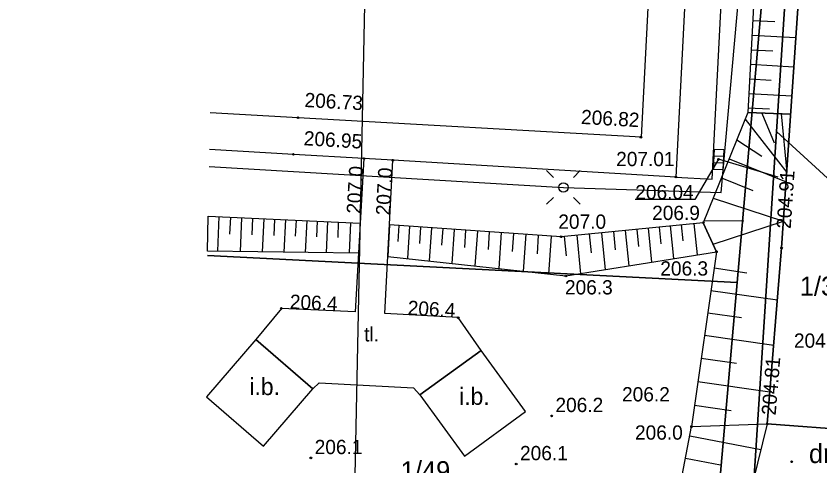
# Model space of a CAD drawing. Extents: x 6512400 to 6513200, y 6022500 to 6022750.
# Drawn here: x 6512691.61 to 6512733.85, y 6022618.44 to 6022642.07 of the extents above; entities that cross this region are included whole.
import ezdxf

# ---------------------------------------------------------------- set-up
doc = ezdxf.new("R2010")
doc.units = 0
for name, color, linetype in [('000 Inne (niezydentyfikowane)', 7, 'Continuous'), ('210-oznaczenie konturu użytku gruntowego', 7, 'Continuous'), ('211-numer działki ewidencyjnej', 7, 'Continuous'), ('217-kontur klasyfikacyjny', 7, 'Continuous'), ('218-kontur użytku gruntowego', 7, 'Continuous'), ('219-działka ewidencyjna', 7, 'Continuous'), ('chodnik (powierzchnia)', 7, 'Continuous'), ('inna budowla (powierzchnia)', 7, 'Continuous'), ('inna budowla (powierzchnia)-Atr17', 7, 'Continuous'), ('jezdnia', 7, 'Continuous'), ('jezdnia (powierzchnia)', 7, 'Continuous'), ('kratka ściekowa (punkt)', 7, 'Continuous'), ('krawężnik (linia)', 7, 'Continuous'), ('latarnia (punkt)', 7, 'Continuous'), ('Obszar opracowania', 7, 'Continuous'), ('pikieta naturalna', 7, 'Continuous'), ('pikieta naturalna-Atr2', 7, 'Continuous'), ('pikieta sztuczna', 7, 'Continuous'), ('pikieta sztuczna-Atr2', 7, 'Continuous'), ('plac (powierzchnia)', 7, 'Continuous'), ('plac (powierzchnia)-Atr17', 7, 'Continuous'), ('przewód elektroenergetyczny (linia)', 7, 'Continuous'), ('przewód kanalizacyjny (linia)', 7, 'Continuous'), ('punkt o określonej wysokości (sieć kanalizacyjna)', 7, 'Continuous'), ('punkt o określonej wysokości (sieć kanalizacyjna)-Atr2', 7, 'Continuous'), ('punkt wysokościowy naturalny', 7, 'Continuous'), ('punkt wysokościowy naturalny-Atr2', 7, 'Continuous'), ('punkt wysokościowy sztuczny', 7, 'Continuous'), ('punkt wysokościowy sztuczny-Atr2', 7, 'Continuous'), ('skarpa nieumocniona', 7, 'Continuous'), ('skarpa nieumocniona (powierzchnia)', 7, 'Continuous')]:
    doc.layers.add(name, color=color, linetype=linetype)

# ---------------------------------------------------------------- blocks, each defined once
blk = doc.blocks.new('PW01')
blk.add_circle((0, 0), 0.045)
blk = doc.blocks.new('PW02')
blk.add_circle((0, 0), 0.045)
blk = doc.blocks.new('US05')
for p, q in [((-0.525, -0.25), (-0.525, 0.25)), ((-0.525, 0.25), (-0.175, 0.25)), ((-0.175, -0.25), (-0.175, 0.25)), ((-0.175, 0.25), (0.175, 0.25)), ((0.175, -0.25), (0.175, 0.25)), ((0.175, 0.25), (0.525, 0.25)), ((0.525, -0.25), (0.525, 0.25)), ((-0.525, -0.25), (-0.175, -0.25)), ((-0.175, -0.25), (0.175, -0.25)), ((0.175, -0.25), (0.525, -0.25))]:
    blk.add_line(p, q)
blk = doc.blocks.new('SM01')
for p, q in [((-0.53, 0.531), (-0.883, 0.884)), ((0.531, 0.531), (0.884, 0.884)), ((-0.53, -0.53), (-0.883, -0.883)), ((0.531, -0.53), (0.884, -0.883))]:
    blk.add_line(p, q)
blk.add_circle((0, 0), 0.25)

msp = doc.modelspace()

# ---------------------------------------------------------------- linework, layer by layer
at = {"layer": '000 Inne (niezydentyfikowane)'}
for p, q in [((6512702.27, 6022631.54), (6512702.19, 6022629.72)), ((6512702.87, 6022631.51), (6512702.83, 6022630.61)), ((6512703.46, 6022631.48), (6512703.38, 6022629.71)), ((6512704.04, 6022631.46), (6512704, 6022630.58)), ((6512704.62, 6022631.43), (6512704.54, 6022629.69)), ((6512705.19, 6022631.4), (6512705.16, 6022630.54)), ((6512705.76, 6022631.38), (6512705.68, 6022629.67)), ((6512706.32, 6022631.35), (6512706.28, 6022630.51)), ((6512706.88, 6022631.33), (6512706.8, 6022629.66)), ((6512707.43, 6022631.3), (6512707.39, 6022630.48)), ((6512707.98, 6022631.28), (6512707.9, 6022629.64)), ((6512708.54, 6022631.25), (6512708.51, 6022630.44)), ((6512709.19, 6022631.22), (6512709.12, 6022629.63)), ((6512727.01, 6022620.02), (6512730.75, 6022619.31)), ((6512726.78, 6022618.84), (6512728.62, 6022618.49))]:
    msp.add_line(p, q, dxfattribs=at)
for points in [[(6512730.32, 6022641.85), (6512731.48, 6022641.79)], [(6512730.27, 6022641.07), (6512732.58, 6022640.95)], [(6512730.23, 6022640.3), (6512731.38, 6022640.24)], [(6512730.19, 6022639.54), (6512732.48, 6022639.41)], [(6512730.15, 6022638.77), (6512731.29, 6022638.71)], [(6512730.11, 6022638.01), (6512732.38, 6022637.89)], [(6512730.07, 6022637.26), (6512731.2, 6022637.2)], [(6512730.79, 6022636.98), (6512731.44, 6022635.42)], [(6512731.81, 6022636.94), (6512732.1, 6022633.85)], [(6512729.92, 6022636.66), (6512732.1, 6022633.85)], [(6512729.48, 6022635.58), (6512730.79, 6022634.71)], [(6512729.08, 6022634.58), (6512732.07, 6022633.37)], [(6512728.68, 6022633.58), (6512730.33, 6022632.91)], [(6512728.24, 6022632.51), (6512731.93, 6022631.3)], [(6512727.77, 6022631.34), (6512729.85, 6022631.32)], [(6512728.23, 6022630.1), (6512731.93, 6022631.3)], [(6512711.72, 6022631.07), (6512711.66, 6022630.23)], [(6512712.28, 6022631.03), (6512712.17, 6022629.34)], [(6512712.86, 6022630.99), (6512712.8, 6022630.13)], [(6512713.44, 6022630.95), (6512713.32, 6022629.21)], [(6512714.03, 6022630.91), (6512713.97, 6022630.03)], [(6512714.63, 6022630.87), (6512714.5, 6022629.08)], [(6512715.23, 6022630.82), (6512715.17, 6022629.92)], [(6512723.62, 6022630.81), (6512723.8, 6022628.95)], [(6512724.22, 6022630.87), (6512724.31, 6022629.96)], [(6512724.82, 6022630.93), (6512724.99, 6022629.14)], [(6512725.4, 6022630.99), (6512725.49, 6022630.11)], [(6512725.98, 6022631.05), (6512726.15, 6022629.33)], [(6512726.56, 6022631.11), (6512726.65, 6022630.26)], [(6512727.22, 6022631.17), (6512727.39, 6022629.53)], [(6512715.85, 6022630.78), (6512715.72, 6022628.95)], [(6512716.47, 6022630.74), (6512716.41, 6022629.81)], [(6512717.1, 6022630.7), (6512716.97, 6022628.81)], [(6512717.74, 6022630.65), (6512717.68, 6022629.7)], [(6512718.39, 6022630.61), (6512718.26, 6022628.67)], [(6512719.05, 6022630.56), (6512718.99, 6022629.58)], [(6512719.72, 6022630.52), (6512719.59, 6022628.52)], [(6512720.41, 6022630.5), (6512720.51, 6022629.47)], [(6512721.07, 6022630.56), (6512721.27, 6022628.54)], [(6512721.73, 6022630.63), (6512721.83, 6022629.64)], [(6512722.37, 6022630.69), (6512722.56, 6022628.75)], [(6512723, 6022630.75), (6512723.09, 6022629.8)], [(6512728.29, 6022628.84), (6512730, 6022628.59)], [(6512728.12, 6022627.66), (6512731.61, 6022627.16)], [(6512727.95, 6022626.49), (6512729.73, 6022626.24)], [(6512727.78, 6022625.31), (6512731.42, 6022624.79)], [(6512727.61, 6022624.11), (6512729.47, 6022623.84)], [(6512727.44, 6022622.88), (6512731.22, 6022622.34)], [(6512727.26, 6022621.63), (6512729.19, 6022621.35)]]:
    msp.add_lwpolyline(points, dxfattribs=at)
at = {"layer": '217-kontur klasyfikacyjny'}
for points in [[(6512729.5, 6022628.07), (6512701.66, 6022629.496)], [(6512727.91, 6022609.85), (6512729.5, 6022628.07)]]:
    msp.add_lwpolyline(points, dxfattribs=at)
at = {"layer": '218-kontur użytku gruntowego'}
for points in [[(6512729.5, 6022628.07), (6512731.23, 6022647.88)], [(6512731.23, 6022647.88), (6512729.5, 6022628.07)], [(6512732.3, 6022647.29), (6512731.57, 6022636.01)], [(6512731.57, 6022636.01), (6512732.3, 6022647.29)], [(6512728.87, 6022594.38), (6512731.57, 6022636.01)], [(6512731.57, 6022636.01), (6512728.87, 6022594.38)], [(6512731.57, 6022636.01), (6512737.73, 6022630.38)], [(6512737.73, 6022630.38), (6512731.57, 6022636.01)], [(6512701.66, 6022629.496), (6512729.5, 6022628.07)], [(6512729.5, 6022628.07), (6512701.66, 6022629.496)], [(6512729.5, 6022628.07), (6512727.91, 6022609.85)], [(6512727.91, 6022609.85), (6512729.5, 6022628.07)]]:
    msp.add_lwpolyline(points, dxfattribs=at)
at = {"layer": '219-działka ewidencyjna'}
for points in [[(6512727.91, 6022609.85), (6512731.23, 6022647.88)], [(6512728.87, 6022594.38), (6512732.3, 6022647.29)]]:
    msp.add_lwpolyline(points, dxfattribs=at)
at = {"layer": 'chodnik (powierzchnia)'}
msp.add_lwpolyline([(6512729.71, 6022662.42), (6512727.8, 6022662.54), (6512726.86, 6022644.89), (6512726.27, 6022633.62), (6512728.18, 6022633.51), (6512728.77, 6022644.78)], close=True, dxfattribs=at)
for points in [[(6512709.89, 6022634.59), (6512706.18, 6022634.81), (6512701.774, 6022635.063)], [(6512726.27, 6022633.62), (6512711.41, 6022634.5)]]:
    msp.add_lwpolyline(points, dxfattribs=at)
at = {"layer": 'inna budowla (powierzchnia)'}
for points in [[(6512707.21, 6022622.49), (6512704.21, 6022625.09), (6512701.62, 6022622.07), (6512704.61, 6022619.47)], [(6512716.05, 6022624.51), (6512712.83, 6022622.17), (6512715.17, 6022618.95), (6512718.37, 6022621.3)]]:
    msp.add_lwpolyline(points, close=True, dxfattribs=at)
at = {"layer": 'jezdnia'}
msp.add_lwpolyline([(6512731.08, 6022620.65), (6512728.82, 6022611.46), (6512722.83, 6022600.42), (6512717.94, 6022592.02), (6512712.43, 6022580.37), (6512709.04, 6022573), (6512712.21, 6022570.83), (6512715.01, 6022579.3), (6512720.33, 6022590.74), (6512725.35, 6022598.98), (6512731.85, 6022610.22), (6512735.75, 6022620.3)], close=True, dxfattribs=at)
at = {"layer": 'jezdnia (powierzchnia)'}
msp.add_lwpolyline([(6512731.22, 6022666.45), (6512731.29, 6022656.48), (6512731.47, 6022656.36), (6512731.64, 6022656.23), (6512731.8, 6022656.1), (6512731.95, 6022655.95), (6512732.1, 6022655.8), (6512732.24, 6022655.64), (6512732.37, 6022655.47), (6512732.49, 6022655.3), (6512732.61, 6022655.12), (6512732.71, 6022654.94), (6512732.81, 6022654.75), (6512732.89, 6022654.55), (6512732.97, 6022654.35), (6512733.03, 6022654.15), (6512733.34, 6022650.68), (6512733.03, 6022646.55), (6512732.9, 6022645.58), (6512731.83, 6022629.89), (6512731.08, 6022620.65), (6512735.75, 6022620.3)], dxfattribs=at)
at = {"layer": 'krawężnik (linia)'}
for points in [[(6512702.473, 6022669.202), (6512710.9, 6022668.72), (6512710.75, 6022664.74), (6512710.88, 6022663.85), (6512711.57, 6022663.54), (6512725.79, 6022662.66), (6512724.94, 6022645.24), (6512724.45, 6022635.71), (6512706.43, 6022636.73), (6512701.814, 6022636.999)], [(6512735.75, 6022620.3), (6512731.08, 6022620.65), (6512731.83, 6022629.89), (6512732.9, 6022645.58), (6512733.03, 6022646.55), (6512733.34, 6022650.68), (6512733.03, 6022654.15), (6512732.97, 6022654.35), (6512732.89, 6022654.55), (6512732.81, 6022654.75), (6512732.71, 6022654.94), (6512732.61, 6022655.12), (6512732.49, 6022655.3), (6512732.37, 6022655.47), (6512732.24, 6022655.64), (6512732.1, 6022655.8), (6512731.95, 6022655.95), (6512731.8, 6022656.1), (6512731.64, 6022656.23), (6512731.47, 6022656.36), (6512731.29, 6022656.48), (6512731.22, 6022666.45)]]:
    msp.add_lwpolyline(points, dxfattribs=at)
at = {"layer": 'Obszar opracowania'}
msp.add_lwpolyline([(6512710.98, 6022693.84), (6512748.35, 6022694.16), (6512798.11, 6022695.25), (6512807.47, 6022695.46), (6512809.66, 6022606.87), (6512863.71, 6022622.03), (6512875.13, 6022581.36), (6512755.22, 6022535.25), (6512691.61, 6022568.03), (6512709.16, 6022605.16)], close=True, dxfattribs=at)
at = {"layer": 'plac (powierzchnia)'}
msp.add_lwpolyline([(6512704.21, 6022625.09), (6512707.21, 6022622.49), (6512707.54, 6022622.81), (6512712.5, 6022622.54), (6512712.83, 6022622.17), (6512716.05, 6022624.51), (6512714.84, 6022626.23), (6512710.99, 6022626.45), (6512711.41, 6022634.5), (6512709.89, 6022634.59), (6512709.42, 6022626.54), (6512705.55, 6022626.72)], close=True, dxfattribs=at)
at = {"layer": 'przewód elektroenergetyczny (linia)'}
msp.add_lwpolyline([(6512701.756, 6022634.173), (6512720.37, 6022633.07), (6512728.65, 6022632.8), (6512729.84, 6022646.1), (6512731.03, 6022668.44), (6512718.53, 6022669.06), (6512712.43, 6022669.64), (6512702.495, 6022670.296)], dxfattribs=at)
at = {"layer": 'przewód kanalizacyjny (linia)'}
msp.add_lwpolyline([(6512731.66, 6022633.61), (6512728.52, 6022634.55)], dxfattribs=at)
at = {"layer": 'punkt o określonej wysokości (sieć kanalizacyjna)-Atr2'}
msp.add_lwpolyline([(6512728.52, 6022634.55), (6512727.28, 6022632.44), (6512724.145, 6022632.44)], dxfattribs=at)
at = {"layer": 'skarpa nieumocniona'}
msp.add_lwpolyline([(6512728.82, 6022611.46), (6512722.83, 6022600.42), (6512717.94, 6022592.02), (6512712.43, 6022580.37), (6512701.7, 6022566.06), (6512698.57, 6022561.61), (6512695.94, 6022556.8), (6512692.31, 6022558.67), (6512695.23, 6022563.7), (6512698.61, 6022570.74), (6512708.72, 6022584.18), (6512714.93, 6022592.74), (6512720.42, 6022602.03), (6512725.72, 6022613.25), (6512727.1, 6022620.51), (6512731.08, 6022620.65)], close=True, dxfattribs=at)
msp.add_lwpolyline([(6512728.82, 6022611.46), (6512722.83, 6022600.42), (6512717.94, 6022592.02), (6512712.43, 6022580.37), (6512701.7, 6022566.06), (6512698.57, 6022561.61), (6512695.94, 6022556.8), (6512692.31, 6022558.67), (6512695.23, 6022563.7), (6512698.61, 6022570.74), (6512708.72, 6022584.18), (6512714.93, 6022592.74), (6512720.42, 6022602.03), (6512725.72, 6022613.25), (6512727.1, 6022620.51), (6512731.08, 6022620.65)], close=True, dxfattribs=at)
at = {"layer": 'skarpa nieumocniona (powierzchnia)'}
for points in [[(6512730.46, 6022644.58), (6512730.06, 6022637.01), (6512732.31, 6022636.92), (6512732.9, 6022645.58), (6512733.03, 6022646.55), (6512733.34, 6022650.68), (6512733.03, 6022654.15), (6512732.81, 6022654.75), (6512732.24, 6022655.64), (6512731.8, 6022656.1), (6512731.39, 6022656.42), (6512730.87, 6022653.56)], [(6512730.46, 6022644.58), (6512730.06, 6022637.01), (6512732.31, 6022636.92), (6512732.9, 6022645.58), (6512733.03, 6022646.55), (6512733.34, 6022650.68), (6512733.03, 6022654.15), (6512732.81, 6022654.75), (6512732.24, 6022655.64), (6512731.8, 6022656.1), (6512731.39, 6022656.42), (6512730.87, 6022653.56)], [(6512727.1, 6022620.51), (6512731.08, 6022620.65), (6512731.83, 6022629.89), (6512732.31, 6022636.92), (6512730.06, 6022637.01), (6512727.72, 6022631.22), (6512728.41, 6022629.69)], [(6512727.1, 6022620.51), (6512731.08, 6022620.65), (6512731.83, 6022629.89), (6512732.31, 6022636.92), (6512730.06, 6022637.01), (6512727.72, 6022631.22), (6512728.41, 6022629.69)], [(6512709.69, 6022631.2), (6512709.6, 6022629.62), (6512701.66, 6022629.73), (6512701.7, 6022631.56)], [(6512709.69, 6022631.2), (6512709.6, 6022629.62), (6512701.66, 6022629.73), (6512701.7, 6022631.56)], [(6512711.15, 6022629.45), (6512720.5, 6022628.42), (6512728.41, 6022629.69), (6512727.72, 6022631.22), (6512720.25, 6022630.48), (6512711.23, 6022631.1)], [(6512711.15, 6022629.45), (6512720.5, 6022628.42), (6512728.41, 6022629.69), (6512727.72, 6022631.22), (6512720.25, 6022630.48), (6512711.23, 6022631.1)]]:
    msp.add_lwpolyline(points, close=True, dxfattribs=at)

# ---------------------------------------------------------------- block references
at = {"layer": 'kratka ściekowa (punkt)', "rotation": -92.408}
msp.add_blockref('US05', (6512728.52, 6022634.55), dxfattribs=at)
at = {"layer": 'latarnia (punkt)'}
msp.add_blockref('SM01', (6512720.37, 6022633.07), dxfattribs=at)
at = {"layer": 'pikieta naturalna'}
for p in [(6512719.75, 6022621.07), (6512727.1, 6022620.51), (6512727.1, 6022620.51)]:
    msp.add_blockref('PW01', p, dxfattribs=at)
at = {"layer": 'pikieta sztuczna'}
msp.add_blockref('PW01', (6512731.08, 6022620.65), dxfattribs=at)
at = {"layer": 'punkt o określonej wysokości (sieć kanalizacyjna)'}
msp.add_blockref('PW01', (6512728.52, 6022634.55), dxfattribs=at)
at = {"layer": 'punkt wysokościowy naturalny'}
for p in [(6512709.89, 6022634.59), (6512711.41, 6022634.5), (6512727.72, 6022631.22), (6512720.25, 6022630.48), (6512728.41, 6022629.69), (6512720.5, 6022628.42), (6512705.55, 6022626.72), (6512714.84, 6022626.23), (6512707.1, 6022618.86), (6512717.89, 6022618.54), (6512732.36, 6022618.66)]:
    msp.add_blockref('PW01', p, dxfattribs=at)
at = {"layer": 'punkt wysokościowy sztuczny'}
for p in [(6512706.42, 6022636.73), (6512724.44, 6022635.71), (6512706.18, 6022634.81), (6512726.27, 6022633.62), (6512731.83, 6022629.89)]:
    msp.add_blockref('PW02', p, dxfattribs=at)

# ---------------------------------------------------------------- texts
at = {"layer": '210-oznaczenie konturu użytku gruntowego'}
msp.add_text('dr', height=1, dxfattribs=at).set_placement((6512733.27, 6022618.59))
at = {"layer": '211-numer działki ewidencyjnej'}
for s, p in [('1/38', (6512732.79, 6022627.39)), ('1/49', (6512711.82, 6022617.69))]:
    msp.add_text(s, height=1, dxfattribs=at).set_placement(p)
at = {"layer": 'inna budowla (powierzchnia)-Atr17'}
for p in [(6512703.87, 6022622.16), (6512714.89, 6022621.65)]:
    msp.add_text('i.b.', height=0.9, dxfattribs=at).set_placement(p)
at = {"layer": 'pikieta naturalna-Atr2'}
for s, p in [('206.2', (6512723.45, 6022621.83)), ('206.2', (6512719.95, 6022621.27)), ('206.0', (6512724.13, 6022619.82))]:
    msp.add_text(s, height=0.75, dxfattribs=at).set_placement(p)
at = {"layer": 'pikieta sztuczna-Atr2'}
msp.add_text('204.80', height=0.75, dxfattribs=at).set_placement((6512732.48, 6022624.65))
msp.add_text('204.81', height=0.75, rotation=85.36, dxfattribs=at).set_placement((6512731.52, 6022621.08))
at = {"layer": 'plac (powierzchnia)-Atr17'}
msp.add_text('tl.', height=0.75, dxfattribs=at).set_placement((6512709.9, 6022624.98))
at = {"layer": 'punkt o określonej wysokości (sieć kanalizacyjna)-Atr2'}
msp.add_text('206.04', height=0.75, dxfattribs=at).set_placement((6512724.145, 6022632.448))
at = {"layer": 'punkt wysokościowy naturalny-Atr2'}
for s, rotation, p in [('207.0', 86.658, (6512709.72, 6022631.67)), ('207.0', 87.013, (6512711.26, 6022631.59)), ('206.4', 357.337, (6512705.98, 6022626.7)), ('206.4', 356.729, (6512712.17, 6022626.38))]:
    msp.add_text(s, height=0.75, rotation=rotation, dxfattribs=at).set_placement(p)
for s, p in [('206.9', (6512725.03, 6022631.36)), ('207.0', (6512720.1, 6022630.9)), ('206.3', (6512725.46, 6022628.44)), ('206.3', (6512720.45, 6022627.45)), ('206.1', (6512707.3, 6022619.06)), ('206.1', (6512718.09, 6022618.74))]:
    msp.add_text(s, height=0.75, dxfattribs=at).set_placement(p)
at = {"layer": 'punkt wysokościowy sztuczny-Atr2'}
for s, rotation, p in [('206.73', 356.76, (6512706.75, 6022637.3)), ('206.82', 356.76, (6512721.28, 6022636.41)), ('206.95', 356.61, (6512706.71, 6022635.29)), ('204.91', 86.094, (6512732.31, 6022630.88))]:
    msp.add_text(s, height=0.75, rotation=rotation, dxfattribs=at).set_placement(p)
msp.add_text('207.01', height=0.75, dxfattribs=at).set_placement((6512723.14, 6022634.19))

doc.saveas('drawing.dxf')
